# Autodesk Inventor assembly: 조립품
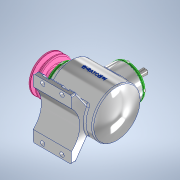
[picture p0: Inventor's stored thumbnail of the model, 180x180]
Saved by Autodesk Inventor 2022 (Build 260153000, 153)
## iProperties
Created: 2023-04
Part Number: 조립품
Document SubType Name: Assembly
Designer: Admin
Author: Admin
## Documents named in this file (17)
- C:\Users\Admin\Desktop\730411V1007\조립품.iam
- C:\Users\Admin\Desktop\730411V1007\본체.ipt
- C:\Users\Admin\Desktop\730411V1007\730411V1007\커버.ipt
- C:\Users\Admin\Desktop\730411V1007\730411V1007\베어링 6203.ipt
- C:\Users\Admin\Desktop\730411V1007\730411V1007\오일실 17 x 32 x 8.ipt
- C:\Users\Admin\Desktop\730411V1007\730411V1007\메인 축.ipt
- 메인 축.ipt
- C:\Users\Admin\Desktop\730411V1007\730411V1007\Ű 5 x 5 x 14.ipt
- C:\Users\Admin\Desktop\730411V1007\730411V1007\메인 베벨기어.ipt
- C:\Users\Admin\Desktop\730411V1007\730411V1007\서브 축.ipt
- 서브 축.ipt
- C:\Users\Admin\Desktop\730411V1007\730411V1007\Ű 4 x 4 x 14.ipt
- C:\Users\Admin\Desktop\730411V1007\730411V1007\서브 베벨기어.ipt
- C:\Users\Admin\Desktop\730411V1007\730411V1007\V-벨트풀리.ipt
- C:\Users\Admin\Desktop\730411V1007\730411V1007\볼트 M4 x 10.ipt
- C:\Users\Admin\Desktop\730411V1007\730411V1007\와셔 4 x 16.ipt
- C:\Users\Admin\Desktop\730411V1007\730411V1007\육각볼트 M4 x 8.ipt
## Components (4 placed, 3 different names)
1. Ű 5 x 5 x 14:1
2. Ű 4 x 4 x 14:1
3. V-벨트풀리:1
4. Ű 4 x 4 x 14:2
